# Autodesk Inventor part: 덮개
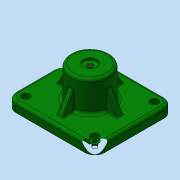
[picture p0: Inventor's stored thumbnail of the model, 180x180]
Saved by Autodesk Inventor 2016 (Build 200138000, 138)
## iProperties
Created: 2017-08
Part Number: 덮개
Material: 알루미늄 6061
Document SubType Name: Modeling
Designer: mduedu
Density: 1 g/cm^3
Appearance: 진녹색
Author: mduedu
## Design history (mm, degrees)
sketch "스케치1"
  geometry: L1 (46, -41)-(-46, -41); L2 (-46, -41)-(-46, 41); L3 (-46, 41)-(46, 41); L4 (46, 41)-(46, -41); 1 further point
  constraints: 8 end point, 2 parallel, 1 horizontal, 1 perpendicular
  dimensions: "d0" = 92 distance of L2.end L3.end; "d2" = 82 distance of L1.end L2.end; "d3" = 41 distance from line of L3 point (0, 0) (= 0.5 x d2); "d4" = 46 distance from line of point (0, 0) L4 (= 0.5 x d0)
extrude "돌출1" new body sketch "스케치1" distance "d5" = 10; taper "d6" = 0 deg
sketch "스케치2"
  geometry: C1 r 20 at (0, 0); 1 further point
  constraints: 1 centre point, 1 coincident
  dimensions: "d55" = 40 diameter of C1
extrude "돌출2" join sketch "스케치2" distance "d9" = 32; taper "d10" = 0 deg
sketch "스케치3"
  geometry: L1 (-26, -26)-(26, -26); L2 (26, -26)-(26, 26); L3 (26, 26)-(-26, 26); L4 (-26, 26)-(-26, -26); L5 (-26, -26)-(26, 26); L6 (26, -26)-(-26, 26); 1 further point
  constraints: 12 end point, 2 midpoint, 2 parallel, 2 perpendicular, 1 horizontal
  dimensions: "d11" = 52 distance of L3.end L2.end
extrude "돌출3" join sketch "스케치3" distance "d12" = 6; taper "d13" = 0 deg
sketch "스케치4"
  geometry: L1 (-17, -17)-(17, -17); L2 (17, -17)-(17, 17); L3 (17, 17)-(-17, 17); L4 (-17, 17)-(-17, -17); L5 (-17, -17)-(17, 17); L6 (17, -17)-(-17, 17); 1 further point
  constraints: 12 end point, 2 midpoint, 2 parallel, 2 perpendicular, 1 horizontal
  dimensions: "d14" = 34 distance of L2.end L3.end
extrude "돌출4" cut sketch "스케치4" distance "d16" = 5; taper "d17" = 0 deg
sketch "스케치5"
  geometry: C1 r 9 at (0, 0); 1 further point
  constraints: 1 centre point, 1 coincident
  dimensions: "d18" = 18 diameter of C1
extrude "돌출5" cut sketch "스케치5" distance "d19" = 34; taper "d20" = 0 deg
sketch "스케치6"
  geometry: 2 further points
  constraints: 1 coincident
hole "구멍1" sketch "스케치6" at (0, 0) diameter "d21" = 5.917; stored, may be unused: countersink angle "d25" = 90 deg, drill point angle "d27" = 118 deg; dims "d22" = 6, "d23" = 14, "d24" = 2, "d26" = 8
fillet "모깎기1" dims "d36" = 10
fillet "모깎기3" dims "d38" = 3
fillet "모깎기4" dims "d39" = 3
fillet "모깎기5" dims "d40" = 3
chamfer "모따기1" distance "d41" = 1; stored, may be unused: second distance "d42" = 2, angle "d43" = 45 deg
fillet "모깎기6" dims "d44" = 3
fillet "모깎기7" dims "d45" = 3
fillet "모깎기8" dims "d46" = 3
sketch "스케치8"
  geometry: A1 r 10 centre (-36, -31) between (-46, -31) and (-36, -41) reference; A2 r 10 centre (-36, 31) between (-36, 41) and (-46, 31) reference; A3 r 10 centre (36, 31) between (46, 31) and (36, 41) reference; A4 r 10 centre (36, -31) between (36, -41) and (46, -31) reference; 5 further points
  constraints: 4 coincident
sketch "스케치9"
  geometry: 4 further points
  constraints: 4 other
hole "구멍3" sketch "스케치9" at (-36, -31), (-36, 31), (36, 31), (36, -31) diameter "d48" = 4.5; stored, may be unused: countersink angle "d52" = 90 deg, drill point angle "d54" = 0 deg; dims "d49" = 6, "d50" = 8, "d51" = 4.6, "d53" = 8
sketch "스케치10"
  geometry: L1 (-7, 40)-(-2.958, 40) reference; L2 (-2.958, 40)-(-2.958, 33) reference; L3 (-2.958, 33)-(-6, 33) reference; L4 (-9, 30)-(-9, -1) reference; L5 (-9, -1)-(-14, -1) reference; L6 (-17, -4)-(-17, -6) reference; L7 (-17, -6)-(-25, -6) reference; L8 (-25, -6)-(-26, -5) reference; L9 (-26, -5)-(-26, 0) reference; L10 (-26, 0)-(-46, 0) reference; L11 (-46, 0)-(-46, 7) reference; L12 (-43, 10)-(-23, 10) reference; L13 (-20, 13)-(-20, 39) reference; L14 (-17, 42)-(-7, 42) reference; L15 (-7, 42)-(-7, 40) reference; L16 (2.958, 40)-(7, 40) reference; L17 (7, 40)-(7, 42) reference; L18 (7, 42)-(17, 42) reference; L19 (20, 39)-(20, 13) reference; L20 (23, 10)-(43, 10) reference; L21 (46, 7)-(46, 0) reference; L22 (46, 0)-(26, 0) reference; L23 (26, 0)-(26, -5) reference; L24 (26, -5)-(25, -6) reference; L25 (25, -6)-(17, -6) reference; L26 (17, -6)-(17, -4) reference; L27 (14, -1)-(9, -1) reference; L28 (9, -1)-(9, 30) reference; L29 (6, 33)-(2.958, 33) reference; L30 (2.958, 33)-(2.958, 40) reference; L31 (31.547, 10)-(20, 30); A1 r 3 centre (-6, 30) between (-6, 33) and (-9, 30) reference; A2 r 3 centre (-14, -4) between (-14, -1) and (-17, -4) reference; A3 r 3 centre (-43, 7) between (-43, 10) and (-46, 7) reference; A4 r 3 centre (-23, 13) between (-23, 10) and (-20, 13) reference; A5 r 3 centre (-17, 39) between (-17, 42) and (-20, 39) reference; A6 r 3 centre (17, 39) between (20, 39) and (17, 42) reference; A7 r 3 centre (23, 13) between (20, 13) and (23, 10) reference; A8 r 3 centre (43, 7) between (46, 7) and (43, 10) reference; A9 r 3 centre (14, -4) between (17, -4) and (14, -1) reference; A10 r 3 centre (6, 30) between (9, 30) and (6, 33) reference; 1 further point
  constraints: 2 end point, 2 point on line
  dimensions: "d56" = 20 distance from line of L31.end L20; "d57" = 120 deg angle of L31 L20
feature "리브1" sketch "스케치10" dims "d58" = 1, "d59" = 6, "d60" = 0, "d61" = 0, "d62" = 1, "d63" = 1
fillet "모깎기9" dims "d64" = 1
fillet "모깎기10" dims "d65" = 1
sketch "스케치11"
  geometry: L1 (36, 53.951)-(105.469, 53.951); L2 (105.469, 53.951)-(105.469, -16.678); L3 (105.469, -16.678)-(36, -16.678); L4 (36, -16.678)-(36, 53.951); 1 further point
  constraints: 8 end point, 2 parallel, 1 horizontal, 1 perpendicular
extrude "돌출6" cut sketch "스케치11" stored distance "d69" = 0; taper "d70" = 0 deg
node "솔리드1"
pattern_circular "원형 패턴1" dims "d67" = 360 deg
node "절단 모서리 투영1"
